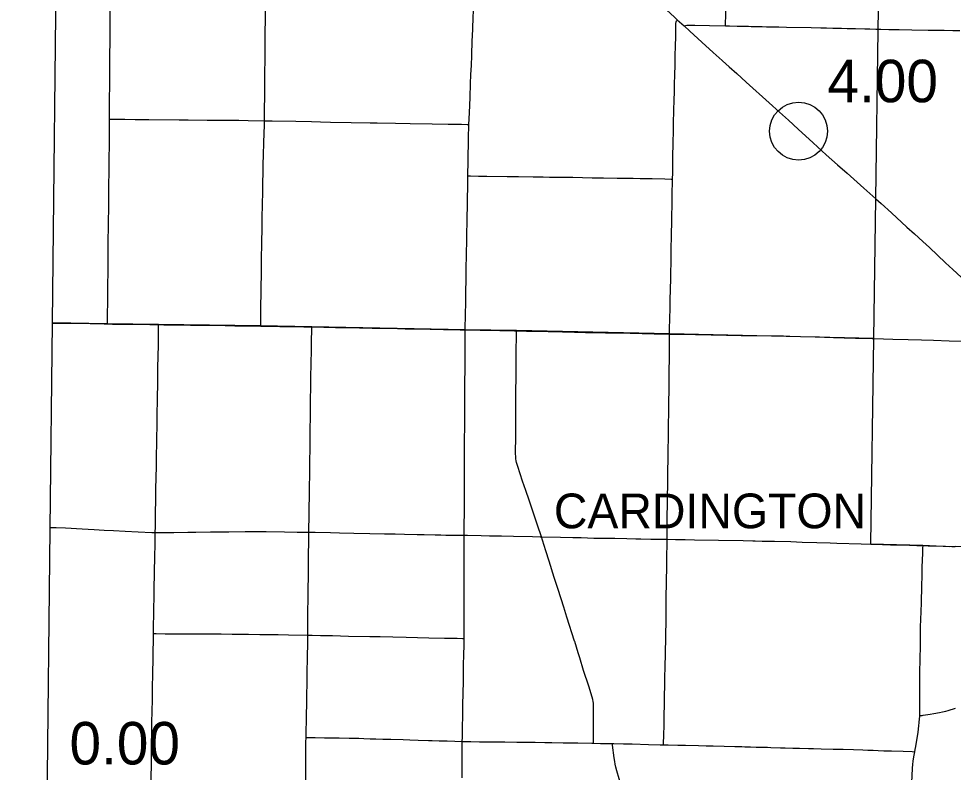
# Model space of a CAD drawing. Extents: x 1813937 to 1948437, y 826606 to 1022856.
# Drawn here: x 1840375 to 1864595, y 920400 to 939932 of the extents above; entities that cross this region are included whole.
import ezdxf

# ---------------------------------------------------------------- set-up
doc = ezdxf.new("R2010")
doc.units = 0
for name, color, linetype in [('Default', 7, 'Continuous'), ('GM_X_County', 7, 'Continuous'), ('GM_X_County_Road', 7, 'Continuous'), ('GM_X_State_Route', 7, 'Continuous'), ('GM_X_Township', 7, 'Continuous'), ('GM_X_Township_Road', 7, 'Continuous'), ('GM_X_Township_Text', 7, 'Continuous')]:
    doc.layers.add(name, color=color, linetype=linetype)

msp = doc.modelspace()

# ---------------------------------------------------------------- linework, layer by layer
at = {"layer": 'Default'}
msp.add_circle((1860585, 937017), 750, dxfattribs=at)
at = {"layer": 'GM_X_County'}
msp.add_lwpolyline([(1839634, 907367), (1840896, 907530), (1840970, 910855), (1841058, 916141), (1841113, 919520), (1841192, 926713), (1841249, 932050), (1841362, 942439)], dxfattribs=at)
at = {"layer": 'GM_X_County_Road'}
for points in [[(1846744, 937289), (1846745, 937386), (1846749, 937632), (1846751, 937879), (1846755, 938518), (1846759, 938879), (1846764, 939371), (1846766, 939650), (1846769, 939830), (1846771, 939945), (1846771, 940142), (1846772, 940470), (1846776, 940765), (1846777, 940978), (1846779, 941142), (1846780, 941405), (1846782, 941634), (1846785, 941946), (1846787, 942126), (1846788, 942340), (1846790, 942611)], [(1852044, 937191), (1852056, 937496), (1852072, 937889), (1852087, 938250), (1852096, 938479), (1852106, 938725), (1852116, 938971), (1852122, 939119), (1852126, 939233), (1852130, 939348), (1852136, 939495), (1852143, 939659), (1852146, 939758), (1852151, 939889), (1852157, 940217)], [(1857322, 935774), (1857325, 935937), (1857331, 936313), (1857338, 936742), (1857344, 937004), (1857348, 937216), (1857356, 937562), (1857363, 937823), (1857366, 938037), (1857373, 938299), (1857375, 938414), (1857378, 938531), (1857384, 938675), (1857386, 938823), (1857390, 938971), (1857397, 939232), (1857403, 939464), (1857408, 939708), (1857408, 939808), (1857413, 939854), (1857419, 939874), (1857428, 939887), (1857441, 939903)], [(1857617, 939744), (1857655, 939753), (1857687, 939761), (1857719, 939765), (1857768, 939767), (1857899, 939765), (1858275, 939757), (1858694, 939749)], [(1858694, 939749), (1858799, 939746), (1858995, 939742), (1859158, 939739), (1859257, 939737), (1859289, 939736), (1859354, 939734), (1859420, 939733), (1859489, 939731), (1859562, 939730), (1859641, 939728), (1859755, 939725), (1859831, 939723), (1860077, 939718), (1860273, 939716), (1860912, 939701), (1861158, 939696), (1861306, 939692), (1861469, 939687), (1861699, 939683), (1861846, 939680), (1862059, 939675), (1862305, 939669), (1862436, 939665), (1862584, 939661), (1862649, 939660)], [(1862649, 939660), (1862715, 939659), (1862928, 939655), (1863190, 939649), (1863518, 939643), (1863944, 939636), (1864124, 939633), (1864354, 939631), (1864583, 939625), (1864764, 939624)], [(1846649, 931965), (1846651, 932155), (1846654, 932401), (1846665, 933385), (1846670, 933746), (1846674, 934074), (1846678, 934254), (1846681, 934386), (1846681, 934582), (1846686, 934812), (1846689, 935074), (1846698, 935484), (1846702, 935698), (1846707, 935927), (1846714, 936173), (1846720, 936386), (1846730, 936731), (1846742, 937173), (1846744, 937289)], [(1846744, 937289), (1846783, 937289), (1846946, 937285), (1847553, 937272), (1847962, 937264), (1848192, 937258), (1848454, 937254), (1848995, 937244), (1849486, 937234), (1849666, 937232), (1850142, 937225), (1850519, 937218), (1851092, 937209), (1851502, 937202), (1851846, 937196), (1851994, 937194), (1852044, 937191)], [(1852018, 935862), (1852023, 936250), (1852027, 936430), (1852031, 936643), (1852035, 936856), (1852043, 937168), (1852044, 937191)], [(1851948, 931868), (1851948, 931903), (1851953, 932248), (1851960, 932592), (1851963, 932888), (1851968, 933134), (1851971, 933462), (1851978, 933806), (1851985, 934216), (1851996, 934807), (1852002, 935053), (1852008, 935315), (1852010, 935528), (1852016, 935790), (1852018, 935862)], [(1857242, 931757), (1857242, 931802), (1857243, 931884), (1857249, 932163), (1857255, 932425), (1857260, 932638), (1857272, 933196), (1857277, 933393), (1857280, 933574), (1857285, 933869), (1857294, 934394), (1857300, 934624), (1857303, 934820), (1857308, 935099), (1857313, 935345), (1857322, 935774)], [(1841253, 932045), (1841389, 932043), (1841620, 932039), (1842230, 932030), (1842593, 932024), (1842679, 932023)], [(1842679, 932023), (1842809, 932019), (1843235, 932014), (1843777, 932005), (1844001, 932003)], [(1844001, 932003), (1844137, 932002), (1844416, 931998), (1844646, 931997), (1844826, 931993), (1845121, 931987), (1845728, 931978), (1845974, 931975), (1846220, 931972), (1846450, 931969), (1846649, 931965)], [(1846649, 931965), (1846909, 931960), (1847139, 931956), (1847385, 931952), (1847762, 931946), (1847973, 931942)], [(1847973, 931942), (1848582, 931932), (1848910, 931925), (1849205, 931920), (1849533, 931912), (1850189, 931901), (1850386, 931897), (1850599, 931894), (1851042, 931886), (1851386, 931879), (1851813, 931871), (1851948, 931868)], [(1851922, 926543), (1851922, 926720), (1851923, 926933), (1851924, 927015), (1851924, 927130), (1851925, 927294), (1851926, 927622), (1851926, 927687), (1851927, 927851), (1851927, 928540), (1851930, 928885), (1851934, 929492), (1851934, 929820), (1851939, 930492), (1851941, 930870), (1851944, 931231), (1851946, 931477), (1851947, 931706), (1851948, 931868)], [(1851948, 931868), (1852338, 931860), (1852846, 931850), (1853223, 931841), (1853277, 931840)], [(1853277, 931840), (1853535, 931835), (1853797, 931830), (1854092, 931824), (1854469, 931816), (1854781, 931809), (1855060, 931802), (1855240, 931799), (1855585, 931792), (1856224, 931778), (1856847, 931767), (1857242, 931757)], [(1857242, 931757), (1857274, 931756), (1857913, 931745), (1858323, 931737), (1858717, 931730), (1859094, 931724), (1859296, 931722)], [(1859296, 931722), (1859439, 931721), (1859898, 931714), (1860193, 931710), (1860357, 931706), (1860636, 931697), (1861128, 931683), (1861255, 931678)], [(1861255, 931678), (1861341, 931674), (1861488, 931668), (1861767, 931661), (1862062, 931654), (1862291, 931648), (1862488, 931644), (1862533, 931642)], [(1862533, 931642), (1862783, 931635), (1863029, 931627), (1863423, 931617), (1863767, 931607), (1864079, 931598), (1864488, 931585), (1864849, 931575), (1864980, 931571), (1865161, 931567), (1865178, 931567)], [(1843868, 923997), (1843868, 924000), (1843872, 924230), (1843875, 924459), (1843878, 924607), (1843884, 924984), (1843888, 925246), (1843893, 925475), (1843898, 925705), (1843901, 925869), (1843904, 926016), (1843908, 926279), (1843914, 926557), (1843915, 926616)], [(1843915, 926616), (1844130, 926614), (1844392, 926616), (1844754, 926622), (1844967, 926626), (1845345, 926630), (1845575, 926633), (1845821, 926635), (1846248, 926640), (1846544, 926641), (1846790, 926639), (1847267, 926632), (1847595, 926626), (1847897, 926623)], [(1847865, 923956), (1847865, 924041), (1847869, 924238), (1847869, 924337), (1847872, 924468), (1847872, 924567), (1847876, 924895), (1847879, 925191), (1847884, 925437), (1847888, 925946), (1847897, 926471), (1847897, 926623)], [(1851917, 923869), (1851917, 923882), (1851918, 923981), (1851918, 924145), (1851918, 924293), (1851919, 924785), (1851920, 925195), (1851919, 925375), (1851918, 925457), (1851918, 925572), (1851919, 925703), (1851921, 925982), (1851921, 926474), (1851922, 926543)], [(1843817, 920623), (1843817, 920640), (1843820, 920984), (1843825, 921443), (1843829, 921722), (1843832, 921951), (1843839, 922312), (1843843, 922591), (1843849, 922951), (1843856, 923361), (1843860, 923558), (1843865, 923787), (1843868, 923997)], [(1847821, 921305), (1847824, 921463), (1847831, 921742), (1847837, 921956), (1847840, 922103), (1847843, 922317), (1847852, 922793), (1847855, 923056), (1847857, 923302), (1847864, 923844), (1847865, 923956)], [(1847865, 923956), (1847919, 923954), (1847984, 923953), (1848198, 923949), (1848509, 923942), (1848919, 923933), (1849477, 923920), (1849740, 923916), (1850068, 923910), (1850412, 923902), (1851003, 923888), (1851413, 923880), (1851741, 923876), (1851872, 923871), (1851917, 923869)], [(1851869, 921200), (1851872, 921308), (1851874, 921390), (1851875, 921521), (1851876, 921603), (1851883, 921832), (1851886, 922013), (1851889, 922209), (1851891, 922390), (1851899, 922816), (1851902, 922997), (1851906, 923210), (1851910, 923423), (1851915, 923718), (1851917, 923869)], [(1847821, 921305), (1847890, 921303), (1848054, 921300), (1848300, 921296), (1848678, 921290), (1848940, 921286), (1849186, 921281), (1849318, 921278), (1849482, 921272), (1849629, 921268), (1849810, 921263), (1850023, 921257), (1850335, 921248), (1850515, 921243), (1850728, 921235), (1850991, 921228), (1851089, 921224), (1851270, 921219), (1851482, 921213), (1851679, 921206), (1851869, 921200)], [(1851870, 920258), (1851869, 920455), (1851870, 920652), (1851867, 921078), (1851869, 921177), (1851869, 921200)], [(1851869, 921200), (1851925, 921198), (1852089, 921195), (1852319, 921193), (1852696, 921189), (1852975, 921187), (1853287, 921182), (1853550, 921180), (1853763, 921178), (1854009, 921176), (1854190, 921173), (1854485, 921168), (1854863, 921162), (1855224, 921154), (1855273, 921153)], [(1855273, 921153), (1855453, 921150), (1855617, 921148), (1855764, 921146)], [(1857023, 916832), (1856919, 917142), (1856769, 917593), (1856674, 917872), (1856604, 918074), (1856517, 918338), (1856448, 918557), (1856339, 918918), (1856184, 919437), (1856121, 919640), (1856035, 919922), (1855938, 920235), (1855877, 920439), (1855850, 920534), (1855831, 920614), (1855820, 920679), (1855806, 920777), (1855767, 921102), (1855766, 921119), (1855764, 921146)], [(1855764, 921146), (1855798, 921145), (1856044, 921141), (1856274, 921136), (1856700, 921124), (1856996, 921116), (1857083, 921114)], [(1857083, 921114), (1857209, 921111), (1857455, 921105), (1857652, 921100), (1857996, 921093), (1858193, 921089), (1858374, 921084), (1858653, 921077), (1858931, 921069), (1859112, 921065), (1859194, 921063), (1859341, 921058), (1859487, 921054), (1859534, 921053), (1859564, 921052), (1859624, 921049), (1859697, 921049), (1859778, 921049), (1859862, 921046), (1860119, 921038), (1860237, 921034), (1860433, 921030), (1860612, 921025), (1860844, 921021), (1860975, 921017), (1861172, 921012), (1861482, 921002), (1861740, 920996), (1862005, 920989), (1862249, 920980), (1862384, 920975), (1862488, 920972)], [(1862488, 920972), (1862514, 920971), (1862645, 920967), (1862795, 920961), (1862991, 920956), (1863299, 920947), (1863532, 920939), (1863596, 920934)], [(1863419, 916883), (1863418, 916971), (1863420, 917102), (1863426, 917322), (1863430, 917511), (1863448, 918330), (1863463, 918805), (1863474, 919116), (1863483, 919345), (1863488, 919462), (1863496, 919623), (1863511, 919983), (1863525, 920310), (1863536, 920506), (1863545, 920604), (1863555, 920686), (1863573, 920799), (1863596, 920934)], [(1843798, 918263), (1843797, 918443), (1843801, 919017), (1843806, 919509), (1843808, 919788), (1843810, 920017), (1843812, 920247), (1843817, 920623)]]:
    msp.add_lwpolyline(points, dxfattribs=at)
at = {"layer": 'GM_X_State_Route'}
for points in [[(1856612, 940668), (1856761, 940529), (1856978, 940328), (1857255, 940073), (1857376, 939962), (1857441, 939903), (1857617, 939744), (1857765, 939609), (1858081, 939323), (1858374, 939060), (1858608, 938848)], [(1858608, 938848), (1858617, 938840), (1858788, 938686), (1858983, 938510), (1859226, 938290), (1859822, 937751), (1860091, 937510), (1860324, 937302), (1860578, 937070), (1860964, 936714), (1861304, 936405), (1861597, 936142), (1861843, 935925), (1862273, 935544), (1862433, 935403), (1862585, 935265), (1862725, 935139), (1862993, 934897), (1863394, 934533), (1863588, 934356), (1863805, 934156), (1863974, 934000), (1864393, 933608), (1864585, 933429), (1864802, 933229)]]:
    msp.add_lwpolyline(points, dxfattribs=at)
at = {"layer": 'GM_X_Township'}
for points in [[(1862681, 942300), (1862643, 939637), (1862581, 935266), (1862529, 931646), (1857238, 931762), (1853272, 931847), (1851942, 931872), (1847971, 931949), (1846644, 931971), (1843997, 932010), (1842672, 932027), (1841249, 932050)], [(1862529, 931646), (1862452, 926319), (1863806, 926284), (1864501, 926257), (1864642, 926260), (1866861, 926186), (1867410, 926171), (1867588, 926156), (1867590, 926005), (1867433, 922134), (1867234, 916844), (1867123, 914163), (1866935, 910696)]]:
    msp.add_lwpolyline(points, dxfattribs=at)
at = {"layer": 'GM_X_Township_Road'}
for points in [[(1842730, 937328), (1842731, 937497), (1842732, 937907), (1842735, 938153), (1842739, 938596), (1842740, 938875), (1842741, 939072), (1842743, 939252), (1842745, 939597), (1842748, 940007), (1842748, 940269), (1842750, 940762), (1842751, 941073), (1842752, 941303), (1842754, 941828), (1842755, 942287), (1842755, 942452), (1842755, 942519)], [(1858694, 939749), (1858700, 940073), (1858705, 940319), (1858726, 941138), (1858749, 942055), (1858756, 942397)], [(1842679, 932023), (1842677, 932119), (1842686, 932743), (1842688, 932972), (1842689, 933102), (1842690, 933297), (1842693, 933543), (1842695, 933724), (1842697, 934003), (1842705, 934708), (1842709, 934987), (1842714, 935348), (1842715, 935627), (1842718, 935955), (1842721, 936184), (1842724, 936365), (1842727, 936595), (1842729, 936824), (1842730, 937136), (1842730, 937328)], [(1842730, 937328), (1842768, 937327), (1842801, 937326), (1842949, 937325), (1843129, 937324), (1843391, 937321), (1843751, 937318), (1844538, 937313), (1844767, 937310), (1845258, 937305), (1845488, 937302), (1846077, 937298), (1846323, 937294), (1846744, 937289)], [(1852018, 935862), (1852064, 935861), (1852080, 935861), (1852294, 935855), (1852507, 935852), (1853032, 935844), (1853213, 935841), (1853328, 935839), (1853705, 935834), (1853745, 935833)], [(1853745, 935833), (1853968, 935830), (1854132, 935829), (1854313, 935827), (1854493, 935826), (1854739, 935821), (1855235, 935810)], [(1855235, 935810), (1855248, 935810), (1855527, 935805), (1855888, 935800), (1856085, 935798), (1856299, 935795), (1856479, 935793), (1856791, 935788), (1857120, 935780), (1857284, 935775), (1857322, 935774)], [(1843915, 926616), (1843917, 926759), (1843918, 926939), (1843923, 927218), (1843925, 927365), (1843927, 927480), (1843933, 927742), (1843943, 928332), (1843948, 928627), (1843953, 928905), (1843957, 929118), (1843961, 929331), (1843967, 929691), (1843972, 930035), (1843979, 930543), (1843985, 930887), (1843994, 931477), (1843999, 931837), (1844001, 931966), (1844001, 931968), (1844001, 932003)], [(1847897, 926623), (1847901, 927101), (1847903, 927282), (1847908, 927528), (1847912, 927823), (1847916, 928085), (1847922, 928512), (1847925, 928742), (1847928, 928889), (1847932, 929283), (1847936, 929611), (1847941, 930005), (1847945, 930431), (1847949, 930661), (1847953, 930973), (1847961, 931366), (1847965, 931563), (1847972, 931886), (1847973, 931908), (1847973, 931942)], [(1853443, 927921), (1853425, 927974), (1853377, 928114), (1853302, 928348), (1853279, 928427), (1853267, 928475), (1853260, 928523), (1853255, 928557), (1853254, 928589), (1853251, 928654), (1853253, 928802), (1853255, 928982), (1853255, 929261), (1853255, 929442), (1853257, 929655), (1853258, 929786), (1853258, 929950), (1853259, 930131), (1853260, 930360), (1853263, 930557), (1853265, 930803), (1853271, 931345), (1853274, 931689), (1853276, 931779), (1853276, 931804), (1853277, 931840)], [(1857176, 926440), (1857176, 926453), (1857179, 926765), (1857184, 927109), (1857186, 927273), (1857190, 927552), (1857195, 927848), (1857201, 928209), (1857204, 928521), (1857206, 928751), (1857211, 929079), (1857215, 929407), (1857221, 929735), (1857224, 929965), (1857228, 930342), (1857232, 930704), (1857238, 931229), (1857241, 931623), (1857241, 931699), (1857242, 931757)], [(1853919, 926504), (1853819, 926809), (1853673, 927244), (1853593, 927477), (1853524, 927679), (1853468, 927850), (1853443, 927921)], [(1841177, 926746), (1841346, 926745), (1841592, 926734), (1842018, 926710), (1842329, 926694), (1842591, 926679), (1842836, 926666), (1843131, 926650), (1843475, 926633), (1843828, 926618), (1843915, 926616)], [(1847897, 926623), (1848062, 926621), (1848456, 926614), (1848686, 926610), (1849063, 926602), (1849474, 926593), (1849851, 926583), (1850130, 926577), (1850376, 926571), (1850704, 926567), (1850885, 926564), (1851164, 926557), (1851312, 926554), (1851445, 926550), (1851461, 926550), (1851559, 926548), (1851773, 926545), (1851887, 926543), (1851922, 926543)], [(1851922, 926543), (1852002, 926543), (1852363, 926536), (1852576, 926532), (1852888, 926526), (1853200, 926519), (1853692, 926510), (1853888, 926505), (1853919, 926504)], [(1853919, 926504), (1854413, 926492), (1854735, 926486), (1854954, 926482), (1855282, 926473), (1855561, 926468), (1855824, 926465), (1856135, 926458), (1856365, 926451), (1856496, 926449), (1856758, 926447), (1857004, 926442), (1857176, 926440)], [(1854779, 923803), (1854583, 924417), (1854498, 924683), (1854352, 925136), (1854253, 925449), (1854119, 925871), (1854036, 926137), (1853947, 926419), (1853919, 926504)], [(1857083, 921114), (1857085, 921152), (1857086, 921169), (1857090, 921333), (1857098, 921645), (1857104, 921907), (1857108, 922120), (1857111, 922268), (1857115, 922432), (1857118, 922596), (1857122, 922842), (1857127, 923154), (1857133, 923450), (1857142, 923926), (1857150, 924352), (1857153, 924549), (1857155, 924713), (1857158, 924910), (1857164, 925337), (1857170, 925747), (1857173, 926010), (1857177, 926305), (1857176, 926440)], [(1857176, 926440), (1857185, 926440), (1857398, 926437), (1857644, 926433), (1857890, 926428), (1858513, 926417), (1859153, 926404), (1859399, 926400), (1859457, 926399)], [(1859457, 926399), (1859645, 926395), (1859957, 926389), (1860383, 926380), (1860678, 926368), (1861055, 926355), (1861400, 926346), (1861580, 926341), (1862203, 926324), (1862456, 926317)], [(1862456, 926317), (1862541, 926315), (1862965, 926300), (1863259, 926292), (1863651, 926282), (1863810, 926277)], [(1863745, 924011), (1863748, 924145), (1863754, 924391), (1863758, 924538), (1863767, 924816), (1863776, 925210), (1863785, 925521), (1863791, 925717), (1863802, 926078), (1863807, 926209), (1863810, 926277)], [(1863810, 926277), (1863947, 926274), (1864392, 926258), (1864557, 926254), (1864647, 926253)], [(1843868, 923997), (1843921, 923996), (1843937, 923996), (1844167, 923993), (1844347, 923993), (1844773, 923992), (1844987, 923990), (1845216, 923989), (1845626, 923985), (1845905, 923983), (1846331, 923978), (1846626, 923975), (1847102, 923968), (1847364, 923964), (1847865, 923956)], [(1863727, 921869), (1863729, 921933), (1863730, 922080), (1863728, 922228), (1863728, 922441), (1863728, 922605), (1863729, 922703), (1863731, 922982), (1863736, 923342), (1863741, 923670), (1863744, 923883), (1863744, 923965), (1863745, 923990), (1863745, 924011)], [(1855273, 921153), (1855272, 921191), (1855270, 921256), (1855269, 921486), (1855272, 921863), (1855273, 922077), (1855272, 922144), (1855268, 922189), (1855263, 922234), (1855250, 922288), (1855234, 922352), (1855146, 922634), (1855016, 923040), (1854914, 923369), (1854875, 923494), (1854783, 923792), (1854779, 923803)], [(1863727, 921869), (1863753, 921873), (1863768, 921874), (1863784, 921876), (1863817, 921880), (1863996, 921905), (1864093, 921921), (1864237, 921951), (1864317, 921968), (1864397, 921987), (1864460, 922006), (1864648, 922065)], [(1863596, 920934), (1863609, 920990), (1863622, 921073), (1863682, 921445), (1863705, 921607), (1863714, 921688), (1863723, 921786), (1863727, 921851), (1863727, 921869)], [(1847782, 916995), (1847782, 917047), (1847783, 917162), (1847788, 917375), (1847791, 917604), (1847800, 918145), (1847802, 918342), (1847805, 918588), (1847807, 918785), (1847808, 919113), (1847807, 919326), (1847807, 919441), (1847806, 919621), (1847809, 919818), (1847809, 919933), (1847812, 920195), (1847812, 920359), (1847816, 920753), (1847818, 921179), (1847821, 921305)]]:
    msp.add_lwpolyline(points, dxfattribs=at)

# ---------------------------------------------------------------- texts
at = {"layer": 'Default'}
for s, p in [('4.00', (1861335, 937767)), ('0.00', (1841692, 920604))]:
    msp.add_text(s, height=1100, dxfattribs=at).set_placement(p)
at = {"layer": 'GM_X_Township_Text'}
msp.add_text('CARDINGTON', height=900, rotation=0, dxfattribs=at).set_placement((1854244, 926725))

doc.saveas('drawing.dxf')
